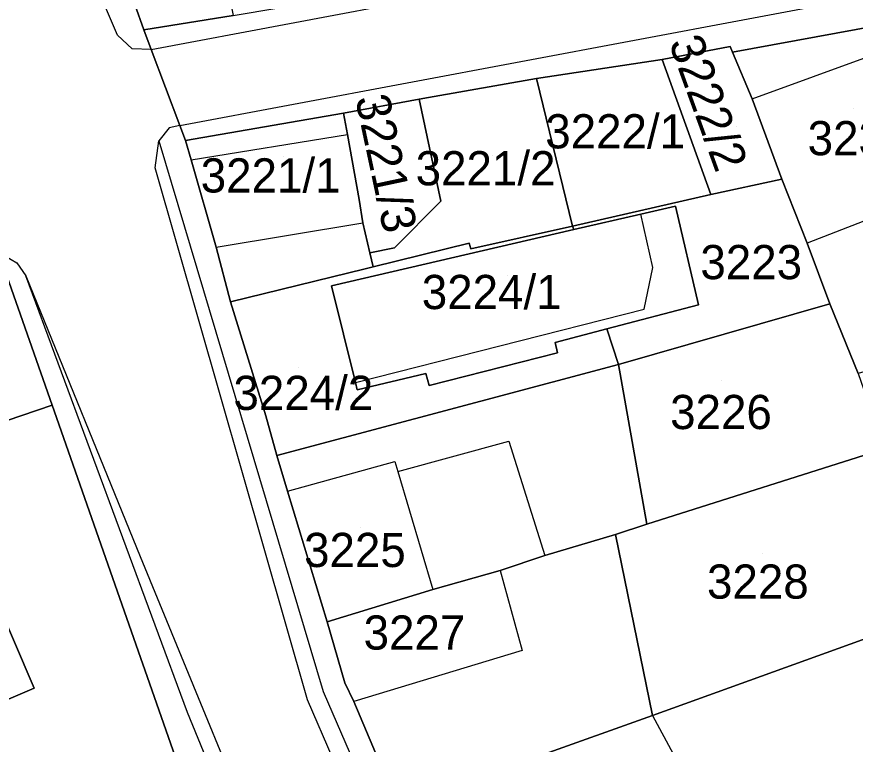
# Model space of a CAD drawing. Extents: x -262657 to -261595, y -1238015 to -1237156.
# Drawn here: x -261942.44 to -261893.39, y -1237748.69 to -1237706.13 of the extents above; entities that cross this region are included whole.
import ezdxf

# ---------------------------------------------------------------- set-up
doc = ezdxf.new("R2010")
doc.units = 0
for name, color, linetype in [('body_kn', 7, 'Continuous'), ('kladpar_druhypozemkov', 7, 'Continuous'), ('kladpar_hranice', 7, 'Continuous'), ('kladpar_parcelnecisla', 7, 'Continuous'), ('kladpar_plochy', 7, 'Continuous'), ('zappar_hrandruhpozemk', 7, 'Continuous')]:
    doc.layers.add(name, color=color, linetype=linetype)

msp = doc.modelspace()

# ---------------------------------------------------------------- linework, layer by layer
at = {"layer": 'body_kn'}
for p, q in [((-261935.01, -1237706.9), (-261935.01, -1237706.9)), ((-261935.01, -1237706.9), (-261935.01, -1237706.9)), ((-261936.55, -1237707.2), (-261936.55, -1237707.2)), ((-261900.7, -1237707.86), (-261900.7, -1237707.86)), ((-261935.68, -1237708), (-261935.68, -1237708)), ((-261934.58, -1237708.05), (-261934.58, -1237708.05)), ((-261934.58, -1237708.05), (-261934.58, -1237708.05)), ((-261900.57, -1237708.21), (-261900.57, -1237708.21)), ((-261900.57, -1237708.21), (-261900.57, -1237708.21)), ((-261904.69, -1237708.62), (-261904.69, -1237708.62)), ((-261904.69, -1237708.62), (-261904.69, -1237708.62)), ((-261912.03, -1237709.75), (-261912.03, -1237709.75)), ((-261918.35, -1237710.85), (-261918.35, -1237710.85)), ((-261918.89, -1237710.95), (-261918.89, -1237710.95)), ((-261899.41, -1237710.94), (-261899.41, -1237710.94)), ((-261899.41, -1237710.94), (-261899.41, -1237710.94)), ((-261923.32, -1237711.77), (-261923.32, -1237711.77)), ((-261923.32, -1237711.77), (-261923.32, -1237711.77)), ((-261933.53, -1237712.62), (-261933.53, -1237712.62)), ((-261932.89, -1237712.5), (-261932.89, -1237712.5)), ((-261932.89, -1237712.5), (-261932.89, -1237712.5)), ((-261923.1, -1237713.01), (-261923.1, -1237713.01)), ((-261934.13, -1237713.38), (-261934.13, -1237713.38)), ((-261932.56, -1237713.37), (-261932.56, -1237713.37)), ((-261932.56, -1237713.37), (-261932.56, -1237713.37)), ((-261932.24, -1237714.5), (-261932.24, -1237714.5)), ((-261932.24, -1237714.5), (-261932.24, -1237714.5)), ((-261934.35, -1237714.96), (-261934.35, -1237714.96)), ((-261897.68, -1237715.63), (-261897.68, -1237715.63)), ((-261901.83, -1237716.52), (-261901.83, -1237716.52)), ((-261922.41, -1237716.81), (-261922.41, -1237716.81)), ((-261917.63, -1237716.92), (-261917.63, -1237716.92)), ((-261903.91, -1237717.2), (-261903.91, -1237717.2)), ((-261905.94, -1237717.67), (-261905.94, -1237717.67)), ((-261922.2, -1237718.18), (-261922.2, -1237718.18)), ((-261909.92, -1237718.37), (-261909.92, -1237718.37)), ((-261909.92, -1237718.37), (-261909.92, -1237718.37)), ((-261909.85, -1237718.58), (-261909.85, -1237718.58)), ((-261930.78, -1237719.6), (-261930.78, -1237719.6)), ((-261930.78, -1237719.6), (-261930.78, -1237719.6)), ((-261920.35, -1237719.64), (-261920.35, -1237719.64)), ((-261915.98, -1237719.37), (-261915.98, -1237719.37)), ((-261896.2, -1237719.38), (-261896.2, -1237719.38)), ((-261921.78, -1237719.94), (-261921.78, -1237719.94)), ((-261915.87, -1237719.71), (-261915.87, -1237719.71)), ((-261942.43, -1237720.52), (-261942.43, -1237720.52)), ((-261922.05, -1237720.88), (-261922.05, -1237720.88)), ((-261921.59, -1237720.76), (-261921.59, -1237720.76)), ((-261905.23, -1237720.8), (-261905.23, -1237720.8)), ((-261941.9, -1237721.28), (-261941.9, -1237721.28)), ((-261924.03, -1237721.87), (-261924.03, -1237721.87)), ((-261924.03, -1237721.87), (-261924.03, -1237721.87)), ((-261929.93, -1237722.81), (-261929.93, -1237722.81)), ((-261929.93, -1237722.81), (-261929.93, -1237722.81)), ((-261902.56, -1237722.98), (-261902.56, -1237722.98)), ((-261894.88, -1237722.93), (-261894.88, -1237722.93)), ((-261894.88, -1237722.93), (-261894.88, -1237722.93)), ((-261905.73, -1237723.24), (-261905.73, -1237723.24)), ((-261907.92, -1237724.39), (-261907.92, -1237724.39)), ((-261910.95, -1237725.18), (-261910.95, -1237725.18)), ((-261910.81, -1237725.79), (-261910.81, -1237725.79)), ((-261907.23, -1237726.48), (-261907.23, -1237726.48)), ((-261918.5, -1237726.99), (-261918.5, -1237726.99)), ((-261922.63, -1237727.52), (-261922.63, -1237727.52)), ((-261922.63, -1237727.52), (-261922.63, -1237727.52)), ((-261922.52, -1237727.96), (-261922.52, -1237727.96)), ((-261918.32, -1237727.7), (-261918.32, -1237727.7)), ((-261940.37, -1237728.85), (-261940.37, -1237728.85)), ((-261927.87, -1237729.47), (-261927.87, -1237729.47)), ((-261913.65, -1237730.96), (-261913.65, -1237730.96)), ((-261927.22, -1237731.79), (-261927.22, -1237731.79)), ((-261927.22, -1237731.79), (-261927.22, -1237731.79)), ((-261920.33, -1237732.15), (-261920.33, -1237732.15)), ((-261920.14, -1237732.73), (-261920.14, -1237732.73)), ((-261926.6, -1237733.88), (-261926.6, -1237733.88)), ((-261926.6, -1237733.88), (-261926.6, -1237733.88)), ((-261905.58, -1237735.82), (-261905.58, -1237735.82)), ((-261907.41, -1237736.41), (-261907.41, -1237736.41)), ((-261935.22, -1237737.7), (-261935.22, -1237737.7)), ((-261911.54, -1237737.64), (-261911.54, -1237737.64)), ((-261914.17, -1237738.53), (-261914.17, -1237738.53)), ((-261914.17, -1237738.53), (-261914.17, -1237738.53)), ((-261918.09, -1237739.63), (-261918.09, -1237739.63)), ((-261924.29, -1237741.53), (-261924.29, -1237741.53)), ((-261924.29, -1237741.53), (-261924.29, -1237741.53)), ((-261912.87, -1237743.2), (-261912.87, -1237743.2)), ((-261923.24, -1237745.09), (-261923.24, -1237745.09)), ((-261941.42, -1237745.41), (-261941.42, -1237745.41)), ((-261924.51, -1237745.6), (-261924.51, -1237745.6)), ((-261925.44, -1237746.09), (-261925.44, -1237746.09)), ((-261922.72, -1237746.19), (-261922.72, -1237746.19)), ((-261932.46, -1237746.83), (-261932.46, -1237746.83)), ((-261905.24, -1237747), (-261905.24, -1237747)), ((-261905.24, -1237747), (-261905.24, -1237747))]:
    msp.add_line(p, q, dxfattribs=at)
at = {"layer": 'kladpar_druhypozemkov'}
for p, q in [((-261893.52, -1237711.49), (-261893.52, -1237711.49)), ((-261907.93, -1237712.27), (-261907.93, -1237712.27)), ((-261900.32, -1237712.57), (-261900.32, -1237712.57)), ((-261914.6, -1237714.24), (-261914.6, -1237714.24)), ((-261926.83, -1237714.32), (-261926.83, -1237714.32)), ((-261919.71, -1237715.37), (-261919.71, -1237715.37)), ((-261899.19, -1237719.4), (-261899.19, -1237719.4)), ((-261913.73, -1237721.24), (-261913.73, -1237721.24)), ((-261925.93, -1237726.65), (-261925.93, -1237726.65)), ((-261901.23, -1237727.39), (-261901.23, -1237727.39)), ((-261922.34, -1237735.98), (-261922.34, -1237735.98)), ((-261898.79, -1237737.55), (-261898.79, -1237737.55)), ((-261918.8, -1237741.25), (-261918.8, -1237741.25))]:
    msp.add_line(p, q, dxfattribs=at)
at = {"layer": 'kladpar_hranice'}
for points in [[(-261942.75, -1237671.05), (-261942.23, -1237673.66), (-261939.7, -1237688.39), (-261938.13, -1237694.52), (-261935.53, -1237705.41), (-261935.01, -1237706.9), (-261934.58, -1237708.05), (-261932.89, -1237712.5), (-261932.56, -1237713.37), (-261932.24, -1237714.5), (-261930.78, -1237719.6), (-261929.93, -1237722.81), (-261927.87, -1237729.47), (-261927.22, -1237731.79), (-261926.6, -1237733.88), (-261924.29, -1237741.53), (-261923.24, -1237745.09), (-261922.72, -1237746.19), (-261920.12, -1237752.32)], [(-261914.09, -1237816.76), (-261923.62, -1237819.21), (-261923.89, -1237818.34), (-261924, -1237817.96), (-261923.67, -1237817.87), (-261913.97, -1237813.57), (-261908.88, -1237811.31), (-261912.8, -1237801.81), (-261914.12, -1237798.61), (-261922.63, -1237778.24), (-261926.09, -1237769.65), (-261929.76, -1237759.16), (-261940.37, -1237728.85), (-261943.02, -1237721.29), (-261943.45, -1237719.94), (-261944.94, -1237715.14), (-261945.5, -1237713.33), (-261947.79, -1237697.89), (-261949.17, -1237690.86), (-261949.54, -1237688.95), (-261951.01, -1237681.71), (-261952.29, -1237673.66)], [(-261935.01, -1237706.9), (-261935.53, -1237705.41), (-261938.13, -1237694.52), (-261939.7, -1237688.39), (-261933.66, -1237687.18), (-261929.78, -1237706.06), (-261935.01, -1237706.9)], [(-261932.56, -1237713.37), (-261932.89, -1237712.5), (-261934.58, -1237708.05), (-261935.01, -1237706.9), (-261929.78, -1237706.06), (-261924.43, -1237705.13), (-261908.87, -1237702.2), (-261905.84, -1237701.66), (-261905.47, -1237701.59), (-261901.89, -1237700.95), (-261900.74, -1237700.72), (-261899.25, -1237700.43), (-261893.08, -1237699.52)], [(-261889.62, -1237706.2), (-261900.57, -1237708.21), (-261900.7, -1237707.86), (-261904.69, -1237708.62), (-261912.03, -1237709.75), (-261918.35, -1237710.85), (-261918.89, -1237710.95), (-261923.32, -1237711.77), (-261932.56, -1237713.37)], [(-261900.57, -1237708.21), (-261889.62, -1237706.2), (-261883.15, -1237724.04), (-261893.22, -1237726.99), (-261894.88, -1237722.93), (-261896.2, -1237719.38), (-261897.68, -1237715.63), (-261899.41, -1237710.94), (-261900.57, -1237708.21)], [(-261904.69, -1237708.62), (-261900.7, -1237707.86), (-261900.57, -1237708.21), (-261899.41, -1237710.94), (-261897.68, -1237715.63), (-261901.83, -1237716.52), (-261904.69, -1237708.62)], [(-261909.92, -1237718.37), (-261912.03, -1237709.75), (-261904.69, -1237708.62), (-261901.83, -1237716.52), (-261909.92, -1237718.37)], [(-261909.92, -1237718.37), (-261915.87, -1237719.71), (-261915.98, -1237719.37), (-261921.59, -1237720.76), (-261921.78, -1237719.94), (-261920.35, -1237719.64), (-261917.63, -1237716.92), (-261918.89, -1237710.95), (-261918.35, -1237710.85), (-261912.03, -1237709.75), (-261909.92, -1237718.37)], [(-261923.32, -1237711.77), (-261918.89, -1237710.95), (-261917.63, -1237716.92), (-261920.35, -1237719.64), (-261921.78, -1237719.94), (-261922.2, -1237718.18), (-261922.41, -1237716.81), (-261923.1, -1237713.01), (-261923.32, -1237711.77)], [(-261929.93, -1237722.81), (-261930.78, -1237719.6), (-261932.24, -1237714.5), (-261932.56, -1237713.37), (-261923.32, -1237711.77), (-261923.1, -1237713.01), (-261922.41, -1237716.81), (-261922.2, -1237718.18), (-261921.78, -1237719.94), (-261921.59, -1237720.76), (-261922.05, -1237720.88), (-261929.93, -1237722.81)], [(-261894.88, -1237722.93), (-261907.23, -1237726.48), (-261907.92, -1237724.39), (-261902.56, -1237722.98), (-261903.91, -1237717.2), (-261905.94, -1237717.67), (-261909.85, -1237718.58), (-261909.92, -1237718.37), (-261901.83, -1237716.52), (-261897.68, -1237715.63), (-261896.2, -1237719.38), (-261894.88, -1237722.93)], [(-261924.03, -1237721.87), (-261909.85, -1237718.58), (-261905.94, -1237717.67), (-261903.91, -1237717.2), (-261902.56, -1237722.98), (-261907.92, -1237724.39), (-261910.95, -1237725.18), (-261910.81, -1237725.79), (-261918.32, -1237727.7), (-261918.5, -1237726.99), (-261922.52, -1237727.96), (-261922.63, -1237727.52), (-261924.03, -1237721.87)], [(-261927.22, -1237731.79), (-261927.87, -1237729.47), (-261929.93, -1237722.81), (-261922.05, -1237720.88), (-261921.59, -1237720.76), (-261915.98, -1237719.37), (-261915.87, -1237719.71), (-261909.92, -1237718.37), (-261909.85, -1237718.58), (-261924.03, -1237721.87), (-261922.63, -1237727.52), (-261922.52, -1237727.96), (-261918.5, -1237726.99), (-261918.32, -1237727.7), (-261910.81, -1237725.79), (-261910.95, -1237725.18), (-261907.92, -1237724.39), (-261907.23, -1237726.48), (-261927.22, -1237731.79)], [(-261986.41, -1237758.24), (-261992.63, -1237738.46), (-261994.68, -1237730.89), (-261943.02, -1237721.29), (-261940.37, -1237728.85), (-261947.49, -1237731.26), (-261941.42, -1237745.41), (-261957.12, -1237752.11), (-261959.31, -1237747.04), (-261986.41, -1237758.24)], [(-261894.88, -1237722.93), (-261893.22, -1237726.99), (-261891.81, -1237731.03), (-261891.68, -1237731.41), (-261905.58, -1237735.82), (-261907.23, -1237726.48), (-261894.88, -1237722.93)], [(-261924.29, -1237741.53), (-261926.6, -1237733.88), (-261927.22, -1237731.79), (-261907.23, -1237726.48), (-261905.58, -1237735.82), (-261907.41, -1237736.41), (-261911.54, -1237737.64), (-261914.17, -1237738.53), (-261918.09, -1237739.63), (-261924.29, -1237741.53)], [(-261979.29, -1237780.53), (-261986.41, -1237758.24), (-261959.31, -1237747.04), (-261957.12, -1237752.11), (-261941.42, -1237745.41), (-261947.49, -1237731.26), (-261940.37, -1237728.85), (-261929.76, -1237759.16), (-261926.09, -1237769.65), (-261979.29, -1237780.53)], [(-261888.53, -1237740.9), (-261891.79, -1237742.14), (-261905.24, -1237747), (-261907.41, -1237736.41), (-261905.58, -1237735.82), (-261891.68, -1237731.41), (-261890.9, -1237734.21), (-261888.53, -1237740.9)], [(-261920.12, -1237752.32), (-261922.72, -1237746.19), (-261923.24, -1237745.09), (-261924.29, -1237741.53), (-261918.09, -1237739.63), (-261914.17, -1237738.53), (-261911.54, -1237737.64), (-261907.41, -1237736.41), (-261905.24, -1237747), (-261918.2, -1237751.63), (-261920.12, -1237752.32)], [(-261920.12, -1237752.32), (-261918.2, -1237751.63), (-261905.24, -1237747), (-261891.79, -1237742.14), (-261888.53, -1237740.9), (-261888.38, -1237741.32), (-261879.2, -1237737.96), (-261878.19, -1237737.65), (-261876.61, -1237737.16), (-261874.12, -1237742.17), (-261870.26, -1237752.98), (-261885.56, -1237759.1), (-261886.5, -1237759.27), (-261888.28, -1237759.8), (-261893.1, -1237761.58), (-261893.41, -1237761.04), (-261899.15, -1237763.26), (-261908.04, -1237766.48), (-261913.16, -1237768.28), (-261915.03, -1237763.93), (-261915.64, -1237762.81), (-261920.12, -1237752.32)]]:
    msp.add_lwpolyline(points, dxfattribs=at)
at = {"layer": 'kladpar_plochy'}
for points in [[(-261942.75, -1237671.05), (-261942.23, -1237673.66), (-261939.7, -1237688.39), (-261938.13, -1237694.52), (-261935.53, -1237705.41), (-261935.01, -1237706.9), (-261934.58, -1237708.05), (-261932.89, -1237712.5), (-261932.56, -1237713.37), (-261932.24, -1237714.5), (-261930.78, -1237719.6), (-261929.93, -1237722.81), (-261927.87, -1237729.47), (-261927.22, -1237731.79), (-261926.6, -1237733.88), (-261924.29, -1237741.53), (-261923.24, -1237745.09), (-261922.72, -1237746.19), (-261920.12, -1237752.32)], [(-261889.62, -1237706.2), (-261900.57, -1237708.21), (-261900.7, -1237707.86), (-261904.69, -1237708.62), (-261912.03, -1237709.75), (-261918.35, -1237710.85), (-261918.89, -1237710.95), (-261923.32, -1237711.77), (-261932.56, -1237713.37), (-261932.89, -1237712.5), (-261934.58, -1237708.05), (-261935.01, -1237706.9), (-261929.78, -1237706.06), (-261924.43, -1237705.13), (-261908.87, -1237702.2), (-261905.84, -1237701.66), (-261905.47, -1237701.59), (-261901.89, -1237700.95), (-261900.74, -1237700.72), (-261899.25, -1237700.43), (-261893.08, -1237699.52)], [(-261929.76, -1237759.16), (-261940.37, -1237728.85), (-261943.02, -1237721.29)]]:
    msp.add_lwpolyline(points, dxfattribs=at)
for points in [[(-261935.01, -1237706.9), (-261935.53, -1237705.41), (-261938.13, -1237694.52), (-261939.7, -1237688.39), (-261933.66, -1237687.18), (-261929.78, -1237706.06)], [(-261900.57, -1237708.21), (-261889.62, -1237706.2), (-261883.15, -1237724.04), (-261893.22, -1237726.99), (-261894.88, -1237722.93), (-261896.2, -1237719.38), (-261897.68, -1237715.63), (-261899.41, -1237710.94)], [(-261904.69, -1237708.62), (-261900.7, -1237707.86), (-261900.57, -1237708.21), (-261899.41, -1237710.94), (-261897.68, -1237715.63), (-261901.83, -1237716.52)], [(-261909.92, -1237718.37), (-261912.03, -1237709.75), (-261904.69, -1237708.62), (-261901.83, -1237716.52)], [(-261909.92, -1237718.37), (-261915.87, -1237719.71), (-261915.98, -1237719.37), (-261921.59, -1237720.76), (-261921.78, -1237719.94), (-261920.35, -1237719.64), (-261917.63, -1237716.92), (-261918.89, -1237710.95), (-261918.35, -1237710.85), (-261912.03, -1237709.75)], [(-261923.32, -1237711.77), (-261918.89, -1237710.95), (-261917.63, -1237716.92), (-261920.35, -1237719.64), (-261921.78, -1237719.94), (-261922.2, -1237718.18), (-261922.41, -1237716.81), (-261923.1, -1237713.01)], [(-261929.93, -1237722.81), (-261930.78, -1237719.6), (-261932.24, -1237714.5), (-261932.56, -1237713.37), (-261923.32, -1237711.77), (-261923.1, -1237713.01), (-261922.41, -1237716.81), (-261922.2, -1237718.18), (-261921.78, -1237719.94), (-261921.59, -1237720.76), (-261922.05, -1237720.88)], [(-261894.88, -1237722.93), (-261907.23, -1237726.48), (-261907.92, -1237724.39), (-261902.56, -1237722.98), (-261903.91, -1237717.2), (-261905.94, -1237717.67), (-261909.85, -1237718.58), (-261909.92, -1237718.37), (-261901.83, -1237716.52), (-261897.68, -1237715.63), (-261896.2, -1237719.38)], [(-261924.03, -1237721.87), (-261909.85, -1237718.58), (-261905.94, -1237717.67), (-261903.91, -1237717.2), (-261902.56, -1237722.98), (-261907.92, -1237724.39), (-261910.95, -1237725.18), (-261910.81, -1237725.79), (-261918.32, -1237727.7), (-261918.5, -1237726.99), (-261922.52, -1237727.96), (-261922.63, -1237727.52)], [(-261927.22, -1237731.79), (-261927.87, -1237729.47), (-261929.93, -1237722.81), (-261922.05, -1237720.88), (-261921.59, -1237720.76), (-261915.98, -1237719.37), (-261915.87, -1237719.71), (-261909.92, -1237718.37), (-261909.85, -1237718.58), (-261924.03, -1237721.87), (-261922.63, -1237727.52), (-261922.52, -1237727.96), (-261918.5, -1237726.99), (-261918.32, -1237727.7), (-261910.81, -1237725.79), (-261910.95, -1237725.18), (-261907.92, -1237724.39), (-261907.23, -1237726.48)], [(-261986.41, -1237758.24), (-261992.63, -1237738.46), (-261994.68, -1237730.89), (-261943.02, -1237721.29), (-261940.37, -1237728.85), (-261947.49, -1237731.26), (-261941.42, -1237745.41), (-261957.12, -1237752.11), (-261959.31, -1237747.04)], [(-261894.88, -1237722.93), (-261893.22, -1237726.99), (-261891.81, -1237731.03), (-261891.68, -1237731.41), (-261905.58, -1237735.82), (-261907.23, -1237726.48)], [(-261924.29, -1237741.53), (-261926.6, -1237733.88), (-261927.22, -1237731.79), (-261907.23, -1237726.48), (-261905.58, -1237735.82), (-261907.41, -1237736.41), (-261911.54, -1237737.64), (-261914.17, -1237738.53), (-261918.09, -1237739.63)], [(-261979.29, -1237780.53), (-261986.41, -1237758.24), (-261959.31, -1237747.04), (-261957.12, -1237752.11), (-261941.42, -1237745.41), (-261947.49, -1237731.26), (-261940.37, -1237728.85), (-261929.76, -1237759.16), (-261926.09, -1237769.65)], [(-261888.53, -1237740.9), (-261891.79, -1237742.14), (-261905.24, -1237747), (-261907.41, -1237736.41), (-261905.58, -1237735.82), (-261891.68, -1237731.41), (-261890.9, -1237734.21)], [(-261920.12, -1237752.32), (-261922.72, -1237746.19), (-261923.24, -1237745.09), (-261924.29, -1237741.53), (-261918.09, -1237739.63), (-261914.17, -1237738.53), (-261911.54, -1237737.64), (-261907.41, -1237736.41), (-261905.24, -1237747), (-261918.2, -1237751.63)], [(-261920.12, -1237752.32), (-261918.2, -1237751.63), (-261905.24, -1237747), (-261891.79, -1237742.14), (-261888.53, -1237740.9), (-261888.38, -1237741.32), (-261879.2, -1237737.96), (-261878.19, -1237737.65), (-261876.61, -1237737.16), (-261874.12, -1237742.17), (-261870.26, -1237752.98), (-261885.56, -1237759.1), (-261886.5, -1237759.27), (-261888.28, -1237759.8), (-261893.1, -1237761.58), (-261893.41, -1237761.04), (-261899.15, -1237763.26), (-261908.04, -1237766.48), (-261913.16, -1237768.28), (-261915.03, -1237763.93), (-261915.64, -1237762.81)]]:
    msp.add_lwpolyline(points, close=True, dxfattribs=at)
at = {"layer": 'zappar_hrandruhpozemk'}
for p, q in [((-261934.58, -1237708.05), (-261870.9, -1237696.02)), ((-261932.89, -1237712.5), (-261869.66, -1237700.6)), ((-261899.41, -1237710.94), (-261891.39, -1237708.01)), ((-261932.24, -1237714.5), (-261923.1, -1237713.01)), ((-261930.78, -1237719.6), (-261922.2, -1237718.18)), ((-261920.14, -1237732.73), (-261913.65, -1237730.96)), ((-261913.65, -1237730.96), (-261911.54, -1237737.64)), ((-261920.14, -1237732.73), (-261918.09, -1237739.63)), ((-261914.17, -1237738.53), (-261912.87, -1237743.2)), ((-261912.87, -1237743.2), (-261922.72, -1237746.19)), ((-261924.51, -1237745.6), (-261870.74, -1237869.97))]:
    msp.add_line(p, q, dxfattribs=at)
for points in [[(-261934.58, -1237708.05), (-261935.68, -1237708), (-261936.55, -1237707.2), (-261938.03, -1237703.73)], [(-261932.89, -1237712.5), (-261933.53, -1237712.62), (-261934.13, -1237713.38)], [(-261934.35, -1237714.96), (-261934.13, -1237713.38), (-261924.51, -1237745.6)], [(-261888.86, -1237714.17), (-261890.75, -1237714.95), (-261889.93, -1237716.93), (-261896.2, -1237719.38)], [(-261857.29, -1237903.53), (-261871.7, -1237870.32), (-261925.44, -1237746.09), (-261934.35, -1237714.96)], [(-261922.63, -1237727.52), (-261905.73, -1237723.24), (-261905.23, -1237720.8), (-261905.94, -1237717.67)], [(-261943.45, -1237719.94), (-261942.43, -1237720.52), (-261941.9, -1237721.28)], [(-261932.46, -1237746.83), (-261941.9, -1237721.28), (-261935.22, -1237737.7), (-261926.63, -1237758.6)], [(-261926.6, -1237733.88), (-261920.33, -1237732.15), (-261920.14, -1237732.73)], [(-261875, -1237886.44), (-261927.55, -1237758.77), (-261932.46, -1237746.83)], [(-261905.24, -1237747), (-261901.34, -1237754.24), (-261891.88, -1237749.38)]]:
    msp.add_lwpolyline(points, dxfattribs=at)

# ---------------------------------------------------------------- texts
at = {"layer": 'kladpar_parcelnecisla'}
for s, rotation, p in [('3222/2', 290, (-261904.312, -1237707.643)), ('3221/3', 282, (-261922.65, -1237710.895))]:
    msp.add_text(s, height=2, rotation=rotation, dxfattribs=at).set_placement(p)
for s, p in [('3222/1', (-261911.523, -1237713.83)), ('3230', (-261896.173, -1237714.23)), ('3221/2', (-261919.103, -1237715.99)), ('3221/1', (-261931.677, -1237716.41)), ('3223', (-261902.448, -1237721.48)), ('3224/1', (-261918.746, -1237723.23)), ('3224/2', (-261929.762, -1237729.13)), ('3226', (-261904.216, -1237730.25)), ('3225', (-261925.631, -1237738.32)), ('3228', (-261902.059, -1237740.17)), ('3227', (-261922.148, -1237743.15))]:
    msp.add_text(s, height=2, dxfattribs=at).set_placement(p)

doc.saveas('drawing.dxf')
